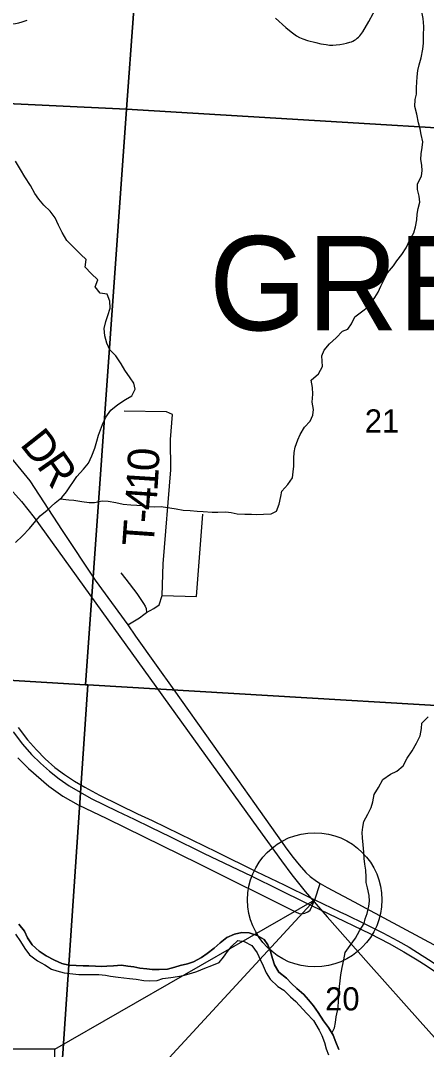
# Model space of a CAD drawing. Extents: x 39.8 to 73.8, y 13 to 35.
# Drawn here: x 45.24 to 45.973, y 29.389 to 31.251 of the extents above; entities that cross this region are included whole.
import ezdxf

# ---------------------------------------------------------------- set-up
doc = ezdxf.new("R2010")
doc.units = 0
for name, color, linetype in [('GM_X_Corporation', 7, 'Continuous'), ('GM_X_County_Road', 7, 'Continuous'), ('GM_X_County_Road_Text', 7, 'Continuous'), ('GM_X_Major_River', 7, 'Continuous'), ('GM_X_Minor_River', 7, 'Continuous'), ('GM_X_Rail_Line', 7, 'Continuous'), ('GM_X_Section_Text', 7, 'Continuous'), ('GM_X_Township_Road', 7, 'Continuous'), ('GM_X_Township_Road_Text', 7, 'Continuous'), ('GM_X_Township_Text', 7, 'Continuous'), ('GM_X_US_Route', 7, 'Continuous'), ('TX_P_1', 7, 'Continuous')]:
    doc.layers.add(name, color=color, linetype=linetype)

msp = doc.modelspace()

# ---------------------------------------------------------------- linework, layer by layer
at = {"layer": 'GM_X_Corporation'}
for points in [[(44.516, 32.1957), (45.5069, 32.1262), (45.4314, 31.091), (44.4392, 31.1377)], [(46.4973, 32.0662), (46.4309, 31.0306), (45.4314, 31.091), (45.5069, 32.1262)], [(45.4314, 31.091), (45.3568, 30.0492), (44.3673, 30.1087), (44.4392, 31.1377)], [(45.4314, 31.091), (46.4309, 31.0306), (46.3565, 29.9898), (45.3612, 30.049), (45.3568, 30.0492)], [(45.3612, 30.049), (46.3565, 29.9898), (46.2858, 28.9647), (45.2916, 29.0179)]]:
    msp.add_lwpolyline(points, close=True, dxfattribs=at)
msp.add_lwpolyline([(44.3588, 29.9766), (44.3673, 30.1087), (45.3568, 30.0492), (45.3612, 30.049), (45.2916, 29.0179), (44.3, 29.0715), (44.3051, 29.1497)], dxfattribs=at)
at = {"layer": 'GM_X_County_Road'}
for points in [[(45.2102, 30.4749), (45.2563, 30.4182), (45.3151, 30.3283), (45.3744, 30.2384), (45.4333, 30.1575), (45.4472, 30.1374), (45.4849, 30.0848), (45.5166, 30.0401), (45.5863, 29.9422), (45.6316, 29.878), (45.6623, 29.8344), (45.7211, 29.7517), (45.7327, 29.7365), (45.7431, 29.7233), (45.7554, 29.7095), (45.7631, 29.7022), (45.7744, 29.6938), (45.7811, 29.6895), (45.7941, 29.6822), (45.8429, 29.6563)], [(45.2348, 29.9173), (45.2538, 29.8979), (45.2907, 29.8655), (45.3163, 29.8476), (45.3439, 29.832), (45.3953, 29.8072), (45.5613, 29.7259), (45.7365, 29.6383), (45.7433, 29.6354), (45.7481, 29.6348), (45.7534, 29.6358), (45.7588, 29.6381), (45.7632, 29.6413), (45.7669, 29.6495), (45.7681, 29.6524)], [(45.7681, 29.6524), (45.7716, 29.6601), (45.7811, 29.6895)], [(45.8429, 29.6563), (45.8641, 29.6449), (46.0264, 29.5578), (46.1656, 29.4834), (46.282, 29.4208), (46.3589, 29.3795), (46.3727, 29.3714), (46.3799, 29.3664)]]:
    msp.add_lwpolyline(points, dxfattribs=at)
at = {"layer": 'GM_X_Major_River'}
for p, q in [((45.2465, 29.6036), (45.2367, 29.6159)), ((45.2523, 29.5912), (45.2465, 29.6036)), ((45.6396, 29.6011), (45.6264, 29.598)), ((45.6532, 29.6001), (45.6396, 29.6011)), ((45.6673, 29.5957), (45.6532, 29.6001)), ((45.2306, 29.5982), (45.2398, 29.585)), ((45.2398, 29.585), (45.2471, 29.5718)), ((45.2607, 29.5784), (45.2523, 29.5912)), ((45.6004, 29.5826), (45.5899, 29.5727)), ((45.6128, 29.5922), (45.6004, 29.5826)), ((45.6264, 29.598), (45.6128, 29.5922)), ((45.6213, 29.5763), (45.6322, 29.5863)), ((45.6322, 29.5863), (45.6439, 29.5849)), ((45.6439, 29.5849), (45.658, 29.5774)), ((45.6802, 29.5886), (45.6673, 29.5957)), ((45.6864, 29.5788), (45.6802, 29.5886)), ((45.2471, 29.5718), (45.2556, 29.5605)), ((45.2733, 29.5671), (45.2607, 29.5784)), ((45.2858, 29.5585), (45.2733, 29.5671)), ((45.5768, 29.5627), (45.567, 29.5558)), ((45.5899, 29.5727), (45.5768, 29.5627)), ((45.6067, 29.5565), (45.6138, 29.5668)), ((45.6138, 29.5668), (45.6213, 29.5763)), ((45.658, 29.5774), (45.6672, 29.5643)), ((45.6672, 29.5643), (45.6737, 29.5507)), ((45.6918, 29.5664), (45.6864, 29.5788)), ((45.6953, 29.5539), (45.6918, 29.5664)), ((45.2556, 29.5605), (45.2704, 29.5497)), ((45.2704, 29.5497), (45.2833, 29.5422)), ((45.3007, 29.5507), (45.2858, 29.5585)), ((45.3143, 29.5448), (45.3007, 29.5507)), ((45.3269, 29.5418), (45.3143, 29.5448)), ((45.5414, 29.5442), (45.5281, 29.541)), ((45.5523, 29.5477), (45.5414, 29.5442)), ((45.567, 29.5558), (45.5523, 29.5477)), ((45.5857, 29.5412), (45.5985, 29.547)), ((45.5985, 29.547), (45.6067, 29.5565)), ((45.6737, 29.5507), (45.678, 29.5409)), ((45.6988, 29.5422), (45.6953, 29.5539)), ((45.2833, 29.5422), (45.2955, 29.5347)), ((45.2955, 29.5347), (45.305, 29.5318)), ((45.305, 29.5318), (45.3187, 29.5281)), ((45.3187, 29.5281), (45.3289, 29.5267)), ((45.3401, 29.5412), (45.3269, 29.5418)), ((45.3289, 29.5267), (45.3448, 29.5253)), ((45.353, 29.5409), (45.3401, 29.5412)), ((45.3448, 29.5253), (45.3595, 29.5251)), ((45.3628, 29.5407), (45.353, 29.5409)), ((45.3595, 29.5251), (45.3709, 29.5252)), ((45.3749, 29.54), (45.3628, 29.5407)), ((45.3709, 29.5252), (45.3811, 29.5249)), ((45.3851, 29.5397), (45.3749, 29.54)), ((45.3954, 29.5402), (45.3851, 29.5397)), ((45.4075, 29.5407), (45.3954, 29.5402)), ((45.4222, 29.5416), (45.4075, 29.5407)), ((45.4336, 29.5402), (45.4222, 29.5416)), ((45.4442, 29.5387), (45.4336, 29.5402)), ((45.4552, 29.5362), (45.4442, 29.5387)), ((45.4677, 29.5352), (45.4552, 29.5362)), ((45.4775, 29.5341), (45.4677, 29.5352)), ((45.4904, 29.5339), (45.4775, 29.5341)), ((45.5055, 29.5347), (45.4904, 29.5339)), ((45.5183, 29.5383), (45.5055, 29.5347)), ((45.5281, 29.541), (45.5183, 29.5383)), ((45.5336, 29.5233), (45.5487, 29.5272)), ((45.5487, 29.5272), (45.5585, 29.5307)), ((45.5585, 29.5307), (45.5728, 29.5365)), ((45.5728, 29.5365), (45.5857, 29.5412)), ((45.678, 29.5409), (45.6838, 29.528)), ((45.6838, 29.528), (45.6911, 29.5167)), ((45.7065, 29.529), (45.6988, 29.5422)), ((45.7202, 29.5181), (45.7065, 29.529)), ((45.3811, 29.5249), (45.3929, 29.5235)), ((45.3929, 29.5235), (45.4023, 29.5217)), ((45.4023, 29.5217), (45.4163, 29.5203)), ((45.4163, 29.5203), (45.4262, 29.5192)), ((45.4262, 29.5192), (45.4368, 29.5178)), ((45.4368, 29.5178), (45.4485, 29.5164)), ((45.4485, 29.5164), (45.4622, 29.5143)), ((45.4622, 29.5143), (45.4735, 29.5136)), ((45.4735, 29.5136), (45.4868, 29.5141)), ((45.4868, 29.5141), (45.497, 29.5176)), ((45.497, 29.5176), (45.5113, 29.5196)), ((45.5113, 29.5196), (45.5234, 29.5213)), ((45.5234, 29.5213), (45.5336, 29.5233)), ((45.6911, 29.5167), (45.7048, 29.5032)), ((45.7297, 29.5087), (45.7202, 29.5181)), ((45.7393, 29.4994), (45.7297, 29.5087)), ((45.7048, 29.5032), (45.7154, 29.4965)), ((45.7154, 29.4965), (45.7277, 29.4845)), ((45.7515, 29.4889), (45.7393, 29.4994)), ((45.7602, 29.4791), (45.7515, 29.4889)), ((45.7277, 29.4845), (45.7376, 29.4762)), ((45.7376, 29.4762), (45.7567, 29.4552)), ((45.769, 29.4686), (45.7602, 29.4791)), ((45.7567, 29.4552), (45.7693, 29.442)), ((45.7775, 29.4561), (45.769, 29.4686)), ((45.7871, 29.4414), (45.7775, 29.4561)), ((45.7693, 29.442), (45.7793, 29.4243)), ((45.7966, 29.429), (45.7871, 29.4414)), ((45.7793, 29.4243), (45.7843, 29.4145)), ((45.7843, 29.4145), (45.7889, 29.4017)), ((45.8047, 29.4154), (45.7966, 29.429)), ((45.8097, 29.4026), (45.8047, 29.4154)), ((45.7889, 29.4017), (45.7924, 29.3907)), ((45.8148, 29.389), (45.8097, 29.4026)), ((45.7924, 29.3907), (45.7963, 29.3798))]:
    msp.add_line(p, q, dxfattribs=at)
for points in [[(45.2367, 29.6159), (45.2465, 29.6036), (45.2523, 29.5912), (45.2607, 29.5784), (45.2733, 29.5671), (45.2858, 29.5585), (45.3007, 29.5507), (45.3143, 29.5448), (45.3269, 29.5418), (45.3401, 29.5412), (45.353, 29.5409), (45.3628, 29.5407), (45.3749, 29.54), (45.3851, 29.5397), (45.3954, 29.5402), (45.4075, 29.5407), (45.4222, 29.5416), (45.4336, 29.5402), (45.4442, 29.5387), (45.4552, 29.5362), (45.4677, 29.5352), (45.4775, 29.5341), (45.4904, 29.5339), (45.5055, 29.5347), (45.5183, 29.5383), (45.5281, 29.541), (45.5414, 29.5442), (45.5523, 29.5477), (45.567, 29.5558), (45.5768, 29.5627), (45.5899, 29.5727), (45.6004, 29.5826), (45.6128, 29.5922), (45.6264, 29.598), (45.6396, 29.6011), (45.6532, 29.6001), (45.6673, 29.5957), (45.6802, 29.5886), (45.6864, 29.5788), (45.6918, 29.5664), (45.6953, 29.5539), (45.6988, 29.5422), (45.7065, 29.529), (45.7202, 29.5181), (45.7297, 29.5087), (45.7393, 29.4994), (45.7515, 29.4889), (45.7602, 29.4791), (45.769, 29.4686), (45.7775, 29.4561), (45.7871, 29.4414), (45.7966, 29.429), (45.8047, 29.4154), (45.8097, 29.4026), (45.8148, 29.389)], [(45.2306, 29.5982), (45.2398, 29.585), (45.2471, 29.5718), (45.2556, 29.5605), (45.2704, 29.5497), (45.2833, 29.5422), (45.2955, 29.5347), (45.305, 29.5318), (45.3187, 29.5281), (45.3289, 29.5267), (45.3448, 29.5253), (45.3595, 29.5251), (45.3709, 29.5252), (45.3811, 29.5249), (45.3929, 29.5235), (45.4023, 29.5217), (45.4163, 29.5203), (45.4262, 29.5192), (45.4368, 29.5178), (45.4485, 29.5164), (45.4622, 29.5143), (45.4735, 29.5136), (45.4868, 29.5141), (45.497, 29.5176), (45.5113, 29.5196), (45.5234, 29.5213), (45.5336, 29.5233), (45.5487, 29.5272), (45.5585, 29.5307), (45.5728, 29.5365), (45.5857, 29.5412), (45.5985, 29.547), (45.6067, 29.5565), (45.6138, 29.5668), (45.6213, 29.5763), (45.6322, 29.5863), (45.6439, 29.5849), (45.658, 29.5774), (45.6672, 29.5643), (45.6737, 29.5507), (45.678, 29.5409), (45.6838, 29.528), (45.6911, 29.5167), (45.7048, 29.5032), (45.7154, 29.4965), (45.7277, 29.4845), (45.7376, 29.4762), (45.7567, 29.4552), (45.7693, 29.442), (45.7793, 29.4243), (45.7843, 29.4145), (45.7889, 29.4017), (45.7924, 29.3907), (45.7963, 29.3798)]]:
    msp.add_lwpolyline(points, dxfattribs=at)
at = {"layer": 'GM_X_Minor_River'}
for p, q in [((45.9654, 29.9795), (45.9767, 29.9913)), ((45.9643, 29.97), (45.9654, 29.9795)), ((45.9553, 29.9438), (45.9624, 29.9571)), ((45.9624, 29.9571), (45.9643, 29.97)), ((45.9474, 29.9297), (45.9553, 29.9438)), ((45.9316, 29.9024), (45.9384, 29.9164)), ((45.9384, 29.9164), (45.9474, 29.9297)), ((45.9199, 29.8929), (45.9316, 29.9024)), ((45.8946, 29.878), (45.9082, 29.8875)), ((45.9082, 29.8875), (45.9199, 29.8929)), ((45.8792, 29.8506), (45.8867, 29.8635)), ((45.8867, 29.8635), (45.8946, 29.878)), ((45.8766, 29.8373), (45.8792, 29.8506)), ((45.8672, 29.8149), (45.8736, 29.8271)), ((45.8736, 29.8271), (45.8766, 29.8373)), ((45.8605, 29.8016), (45.8672, 29.8149)), ((45.8575, 29.7819), (45.8582, 29.7914)), ((45.8582, 29.7914), (45.8605, 29.8016)), ((45.8576, 29.7724), (45.8575, 29.7819)), ((45.8588, 29.7595), (45.8576, 29.7724)), ((45.8603, 29.7466), (45.8588, 29.7595)), ((45.8608, 29.7349), (45.8603, 29.7466)), ((45.8619, 29.7246), (45.8608, 29.7349)), ((45.8639, 29.714), (45.8619, 29.7246)), ((45.8643, 29.7011), (45.8639, 29.714)), ((45.8647, 29.6912), (45.8643, 29.7011)), ((45.8667, 29.6818), (45.8647, 29.6912)), ((45.8701, 29.6681), (45.8667, 29.6818)), ((45.8695, 29.6484), (45.8706, 29.6579)), ((45.8706, 29.6579), (45.8701, 29.6681)), ((45.8665, 29.6355), (45.8695, 29.6484)), ((45.8609, 29.6172), (45.8627, 29.6256)), ((45.8627, 29.6256), (45.8665, 29.6355)), ((45.8452, 29.5905), (45.8522, 29.6038)), ((45.8522, 29.6038), (45.8609, 29.6172)), ((45.8354, 29.5772), (45.8452, 29.5905)), ((45.8239, 29.5513), (45.8268, 29.5646)), ((45.8268, 29.5646), (45.8354, 29.5772)), ((45.821, 29.5376), (45.8239, 29.5513)), ((45.8185, 29.5247), (45.821, 29.5376)), ((45.816, 29.5031), (45.8175, 29.5137)), ((45.8175, 29.5137), (45.8185, 29.5247)), ((45.8147, 29.4777), (45.8154, 29.4925)), ((45.8154, 29.4925), (45.816, 29.5031)), ((45.8137, 29.4648), (45.8147, 29.4777)), ((45.8105, 29.4485), (45.8137, 29.4648)), ((45.8072, 29.4287), (45.809, 29.4382)), ((45.809, 29.4382), (45.8105, 29.4485)), ((45.8027, 29.4188), (45.8072, 29.4287))]:
    msp.add_line(p, q, dxfattribs=at)
for points in [[(45.958, 31.1607), (45.9602, 31.171), (45.964, 31.1839), (45.9669, 31.1995), (45.968, 31.2101), (45.9683, 31.2234), (45.969, 31.2404), (45.9674, 31.2548), (45.9651, 31.2666), (45.962, 31.2802), (45.9605, 31.2954), (45.9593, 31.3053), (45.9585, 31.3159)], [(45.3111, 30.3857), (45.3267, 30.3841), (45.3362, 30.3834), (45.3506, 30.3808), (45.3635, 30.3789), (45.3733, 30.379), (45.3873, 30.382), (45.3979, 30.3813), (45.4116, 30.3791), (45.4252, 30.3761), (45.4388, 30.3746), (45.4498, 30.3743), (45.4601, 30.3735), (45.4695, 30.3721), (45.4816, 30.3713), (45.4938, 30.3721), (45.521, 30.3677), (45.5339, 30.3654), (45.546, 30.3643), (45.5589, 30.3636), (45.5695, 30.3625), (45.5858, 30.3614), (45.596, 30.3615), (45.6108, 30.3619), (45.6203, 30.3608), (45.6313, 30.3585), (45.6453, 30.3578), (45.657, 30.3582), (45.6669, 30.3575), (45.679, 30.3579), (45.6926, 30.3584), (45.7024, 30.3633), (45.7073, 30.3762), (45.7099, 30.3899), (45.7121, 30.3994), (45.7231, 30.4116), (45.731, 30.4237), (45.7324, 30.4343), (45.7335, 30.445), (45.7334, 30.4594), (45.7345, 30.4696), (45.7364, 30.4791), (45.7409, 30.4924), (45.745, 30.5019), (45.7529, 30.5156), (45.7635, 30.5262), (45.7683, 30.5369), (45.7694, 30.5475), (45.7671, 30.5608), (45.7682, 30.5748), (45.7677, 30.5873), (45.765, 30.6002), (45.7782, 30.612), (45.7854, 30.6249), (45.7845, 30.6447), (45.7887, 30.6545), (45.7981, 30.6663), (45.8101, 30.677), (45.8214, 30.6892), (45.8313, 30.6926), (45.8377, 30.7025), (45.8437, 30.715), (45.8558, 30.7238), (45.8686, 30.7337), (45.8803, 30.7497), (45.8859, 30.7599), (45.8911, 30.7706), (45.8968, 30.7827), (45.9028, 30.7949), (45.9141, 30.8071), (45.9201, 30.8166), (45.9291, 30.828), (45.937, 30.8401), (45.9434, 30.8542), (45.9509, 30.8667), (45.9535, 30.8781), (45.9558, 30.8903), (45.9565, 30.9005), (45.9587, 30.9111), (45.9613, 30.9225), (45.9601, 30.9335), (45.957, 30.9453), (45.957, 30.9548), (45.9645, 30.9699), (45.966, 30.9794), (45.9652, 30.9897), (45.9636, 30.9995), (45.964, 31.0102), (45.9658, 31.0215), (45.9669, 31.0318), (45.9638, 31.0447), (45.9619, 31.0549), (45.9588, 31.0659), (45.9561, 31.0818), (45.9522, 31.0955), (45.9533, 31.1084), (45.9552, 31.1179), (45.9555, 31.13), (45.9562, 31.1395), (45.9565, 31.149), (45.958, 31.1607)], [(45.2305, 30.3064), (45.2429, 30.319), (45.2558, 30.3323), (45.2674, 30.3456), (45.2753, 30.3551), (45.2878, 30.3654), (45.3021, 30.3784), (45.3142, 30.3883), (45.3225, 30.3982), (45.3413, 30.4263), (45.3537, 30.4396), (45.3624, 30.4503), (45.3684, 30.4632), (45.3737, 30.4776), (45.3774, 30.4901), (45.3807, 30.5011), (45.3875, 30.5201), (45.3935, 30.5334), (45.4029, 30.5464), (45.4157, 30.5563), (45.4293, 30.5654), (45.4406, 30.5719), (45.4467, 30.5844), (45.4443, 30.5947), (45.4375, 30.6049), (45.428, 30.6185), (45.4215, 30.6302), (45.4116, 30.6443), (45.4009, 30.6552), (45.3956, 30.6673), (45.3921, 30.6806), (45.3909, 30.6939), (45.3935, 30.7068), (45.3976, 30.7174), (45.4017, 30.7307), (45.4013, 30.7436), (45.3959, 30.7561), (45.3834, 30.7576), (45.3747, 30.7693), (45.3792, 30.7822), (45.367, 30.7936), (45.3563, 30.8049), (45.3582, 30.8186), (45.3487, 30.8277), (45.3365, 30.8401), (45.3232, 30.8534), (45.3148, 30.8674), (45.3083, 30.881), (45.3022, 30.8939), (45.293, 30.906), (45.2816, 30.917), (45.2729, 30.9279), (45.2656, 30.9382), (45.2573, 30.9529), (45.2473, 30.9684), (45.2397, 30.9813), (45.2306, 30.9968)]]:
    msp.add_lwpolyline(points, dxfattribs=at)
at = {"layer": 'GM_X_Rail_Line'}
msp.add_lwpolyline([(44.5671, 30.953), (44.7292, 30.8182), (45.0124, 30.5825), (45.1026, 30.5077), (45.1987, 30.4263), (45.2077, 30.4171), (45.22, 30.4044), (45.2312, 30.3923), (45.2411, 30.381), (45.2642, 30.3518), (45.5741, 29.9214), (45.6686, 29.79), (45.7115, 29.7307), (45.7298, 29.7054), (45.754, 29.6754), (45.794, 29.6292), (45.8686, 29.5449), (45.9623, 29.4402), (46.0662, 29.3238)], dxfattribs=at)
at = {"layer": 'GM_X_Township_Road'}
for points in [[(45.7008, 31.2555), (45.7191, 31.2388), (45.7286, 31.2307), (45.7335, 31.227), (45.7387, 31.2236), (45.7441, 31.2206), (45.7498, 31.2181), (45.7587, 31.2152), (45.7736, 31.2111), (45.7827, 31.209), (45.7919, 31.2075), (45.7981, 31.2068), (45.8043, 31.2067), (45.8105, 31.207), (45.8166, 31.2078), (45.8233, 31.2092), (45.8288, 31.2103), (45.8348, 31.2118), (45.8377, 31.2128), (45.8406, 31.214), (45.8433, 31.2155), (45.8459, 31.2171), (45.8484, 31.219), (45.8506, 31.2211), (45.8528, 31.2233), (45.8547, 31.2257), (45.8582, 31.2308), (45.8692, 31.2493), (45.8852, 31.2782)], [(44.9483, 31.2548), (44.9785, 31.2477), (44.9845, 31.2462), (44.9965, 31.2436), (45.0049, 31.2424), (45.0138, 31.242), (45.0276, 31.2416), (45.0615, 31.2415), (45.1026, 31.2415), (45.1542, 31.2423), (45.2066, 31.2438), (45.2188, 31.2446), (45.2307, 31.2459), (45.2367, 31.247), (45.2427, 31.2486), (45.2514, 31.2516)], [(45.4333, 30.1575), (45.4544, 30.1704), (45.4624, 30.1765), (45.4673, 30.1799), (45.4804, 30.1873), (45.49, 30.1939), (45.4955, 30.211), (45.4973, 30.2682), (45.5116, 30.4384), (45.511, 30.4933), (45.5145, 30.538), (45.5032, 30.5431), (45.4272, 30.5442)], [(45.4955, 30.211), (45.558, 30.2091), (45.5692, 30.3578)], [(45.4211, 30.252), (45.4301, 30.2402), (45.4496, 30.2142), (45.462, 30.1965), (45.465, 30.1914), (45.467, 30.1873), (45.4673, 30.1799)]]:
    msp.add_lwpolyline(points, dxfattribs=at)
at = {"layer": 'GM_X_US_Route'}
for points in [[(45.2354, 29.9721), (45.252, 29.9499), (45.2683, 29.9313), (45.2844, 29.9153), (45.3017, 29.8997), (45.3191, 29.8866), (45.3371, 29.8749), (45.356, 29.8637), (45.3825, 29.8495), (45.4177, 29.8321), (45.4512, 29.816), (45.4775, 29.8035), (45.5272, 29.7793), (45.5938, 29.7467), (45.6656, 29.7114), (45.7161, 29.6874), (45.765, 29.6632), (45.7716, 29.6601), (45.8167, 29.6385), (45.8288, 29.6328)], [(45.2265, 29.964), (45.2431, 29.9418), (45.2594, 29.9232), (45.2755, 29.9073), (45.2917, 29.8929), (45.3096, 29.8789), (45.3274, 29.8664), (45.3471, 29.8549), (45.3675, 29.8435), (45.4141, 29.8208), (45.445, 29.8058), (45.4745, 29.7915), (45.5106, 29.7738), (45.5718, 29.7437), (45.6566, 29.7033), (45.7077, 29.6782), (45.7529, 29.6561), (45.7669, 29.6495), (45.811, 29.6283), (45.8248, 29.6216)], [(45.8248, 29.6216), (45.8423, 29.6131), (45.8712, 29.5989), (45.9063, 29.581), (45.9326, 29.5658), (45.9568, 29.5514), (45.9728, 29.5411), (46.0328, 29.5008), (46.0886, 29.4625), (46.1427, 29.4249), (46.1696, 29.4065)], [(45.8288, 29.6328), (45.8611, 29.6174), (45.8944, 29.6003), (45.9218, 29.5857), (45.9422, 29.5742), (45.9658, 29.5595), (45.9817, 29.5492), (46.0418, 29.5089), (46.0975, 29.4705), (46.1516, 29.433), (46.2155, 29.3891), (46.2813, 29.3437), (46.3223, 29.3156)]]:
    msp.add_lwpolyline(points, dxfattribs=at)
at = {"layer": 'TX_P_1'}
for points in [[(45.3015, 29.3899), (45.7716, 29.6601), (45.3015, 29.1497)], [(43.9655, 29.1497), (45.3015, 29.1497), (45.3015, 29.3899), (43.9655, 29.3899)]]:
    msp.add_lwpolyline(points, close=True, dxfattribs=at)
msp.add_circle((45.7716, 29.6601), 0.1215, dxfattribs=at)

# ---------------------------------------------------------------- texts
at = {"layer": 'GM_X_County_Road_Text'}
for s, rotation, p in [('D', 308.3549, (45.2371, 30.4837)), ('R', 304.8657, (45.2676, 30.4453))]:
    msp.add_text(s, height=0.0568, rotation=rotation, dxfattribs=at).set_placement(p)
at = {"layer": 'GM_X_Section_Text'}
for s, p in [('21', (45.862, 30.5057)), ('20', (45.7903, 29.46))]:
    msp.add_text(s, height=0.04186, rotation=0, dxfattribs=at).set_placement(p)
at = {"layer": 'GM_X_Township_Road_Text'}
for s, rotation, p in [('0', 87.5564, (45.4893, 30.4348)), ('1', 86.35, (45.487, 30.3988)), ('4', 85.9779, (45.4846, 30.3638)), ('-', 85.9528, (45.4829, 30.3407)), ('T', 85.9528, (45.48, 30.2984))]:
    msp.add_text(s, height=0.0568, rotation=rotation, dxfattribs=at).set_placement(p)
at = {"layer": 'GM_X_Township_Text'}
msp.add_text('GREEN', height=0.17045, rotation=0, dxfattribs=at).set_placement((45.5803, 30.6907))

doc.saveas('drawing.dxf')
